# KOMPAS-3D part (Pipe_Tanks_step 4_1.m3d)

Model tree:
1. X Axis
2. Y Axis
3. Z Axis  (labels: Pipe Dn 150)
     Òîëùèíà ñòåíêè 1 = 1

Referenced files in C:\Documents and Settings\kashirsky\Мои документы\Camtasia Studio\Pipelines3D\Tanks\: Tanks_step 4.a3d
Referenced files in C:\Program Files\ASCON\KOMPAS-3D V10\Libs\Piping\LOAD\: Piping_C_Pipe_150_1000.m3d
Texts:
  Pipe Dn 150
  Steel ASTM A295
  Three Point Plane
  Plane at Angle
  Line and Point Plane
  Axis through Two Vertices
  Axis of Feature
  Axis of Conical Surface
  Axis through Edge
  Trim by Surface
  Trim by Sketch
  Feature with No History
  Intersection Axis of Two Planes
  Two Line Plane
  Line and Face Plane
  Bend by line
  Hole in sheet body
  Cut in sheet body
  Point in CM
  Linear Dimension from Line to Point
  Surface Finish Symbol
  Geometric Tolerance Symbol
  Leader #1
  Leader #2
  Leader #3
  Shape Deviations and Datum
  Node point number
  Mark of coordination axis
  Node point designation
  Mark/Reference designation with leader
  Mark/reference designation on line
  Mark/Reference designation without leader
  Plane of section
